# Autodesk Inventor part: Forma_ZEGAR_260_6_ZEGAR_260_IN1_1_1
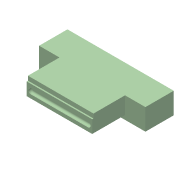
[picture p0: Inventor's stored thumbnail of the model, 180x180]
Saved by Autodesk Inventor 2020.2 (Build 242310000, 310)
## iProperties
Created: 2015-01
Part Number: Forma_ZEGAR_260_6_ZEGAR_260_IN1_1_1
Material: Ogólny
Document SubType Name: Modeling
Designer: F.Stasiak
Density: 1 g/cm^3
Appearance: Domyślna
Catalog Web Link: www.expertbooks.pl
Manager: www.cadconsulting.pl
Company: Fabian Stasiak CAD Consulting
Author: F.Stasiak
Subject: Zbiór ćwiczeń. Autodesk Inventor 2020. Kurs Professional
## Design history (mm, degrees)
node "Forma_ZEGAR_260_4_ZEGAR_260_IN1_Base"
feature "Bryła1::Forma_ZEGAR_260_4_ZEGAR_260_IN1_Base"
tag "Bryła wyprowadzona1"
node "Bryła1"
feature "Forma_ZEGAR_260_4_ZEGAR_260_IN1_Base_Bodies"
